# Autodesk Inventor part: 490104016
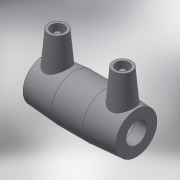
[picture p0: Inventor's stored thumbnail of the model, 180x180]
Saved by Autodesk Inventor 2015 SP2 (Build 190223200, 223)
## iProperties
Created: 2017-06
Part Number: 490104016
Material: Generic
Description: PLASSON COUPLER 16-16
Document SubType Name: Modeling
Designer: KIM
Mass: 55.0731 g
Surface Area: 148.067 cm^2
Volume: 55.0731 cm^3
Density: 1 g/cm^3
Appearance: Default
Author: KIM
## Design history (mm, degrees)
derived "490104.ipt"
feature "Solid1::490104.ipt"
tag "TaggingFeature1"
body "Solid1"
other parameters: "d0" = 71, "d1" = 16, "d2" = 35, "d3" = 34, "d4" = 23.66667, "d5" = 31.5, "d6" = 15.2, "d7" = 16, "d8" = 168 deg, "d10" = 13.6, "d11" = 4.53333, "d13" = 71, "d14" = 17.6296, "d15" = 34, "d16" = 34, "d17" = 15.2, "d18" = 16, "d19" = 3.52592, "d20" = 168 deg, "d22" = 32.9, "d23" = 35, "d24" = 31.913, "d25" = 135 deg, "d26" = 28.4, "d27" = 135 deg, "d29" = 39, "d30" = 14, "d31" = 24.85, "d34" = 5 deg, "d35" = 15, "d39" = 5 deg, "d41" = 4, "d42" = 14, "d43" = 0, "d45" = 4, "d46" = 14, "d47" = 0, "d48" = 3, "d49" = 0, "d50" = 3, "d51" = 0, "d52" = 9.86, "d53" = 2.465, "d_" = 16, "L_" = 71, "L_1" = 34, "D_" = 35, "A_" = 39, "d_2" = 12
